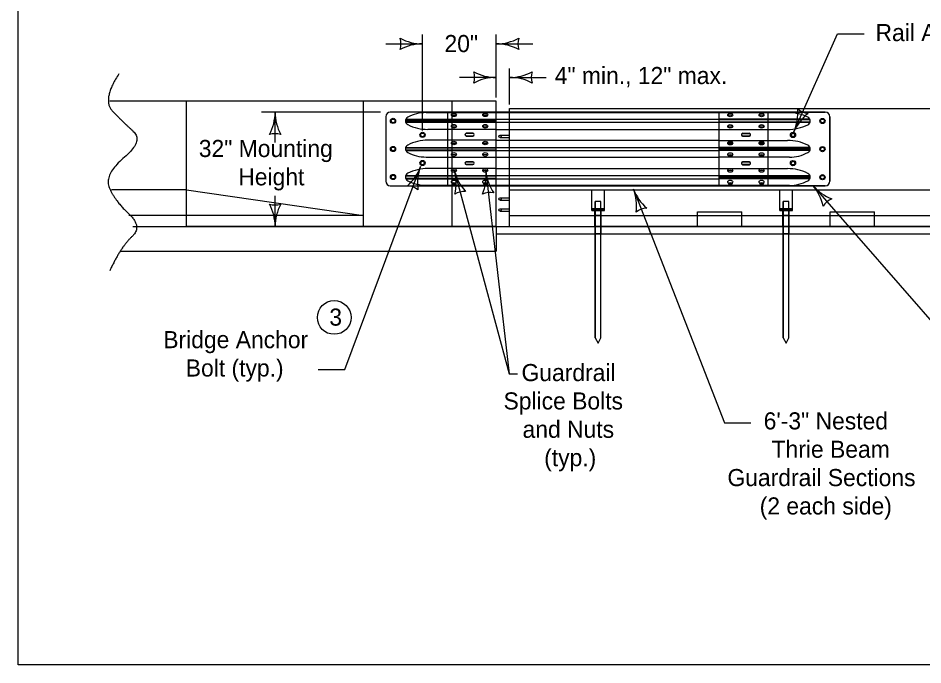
# Model space of a CAD drawing. Extents: x 10028 to 81668, y 3581 to 11018.
# Drawn here: x 20933 to 21737, y 7924 to 8499 of the extents above; entities that cross this region are included whole.
import ezdxf

# ---------------------------------------------------------------- set-up
doc = ezdxf.new("R2010")
doc.units = 0
for name, color, linetype in [('conPaving', 7, 'Continuous'), ('dsnCellsNorthArrow', 7, 'Continuous'), ('dsnTextTabulation', 7, 'Continuous'), ('Level 41', 7, 'Continuous'), ('Level 9', 7, 'Continuous'), ('SheetBorder', 7, 'Continuous')]:
    doc.layers.add(name, color=color, linetype=linetype)

msp = doc.modelspace()

# ---------------------------------------------------------------- linework, layer by layer
at = {"layer": 'conPaving'}
for p, q in [((21357.6, 8415.38), (21263.39, 8415.38)), ((21555.84, 8415.38), (21357.6, 8415.38)), ((21650.05, 8415.38), (21555.84, 8415.38)), ((21259.29, 8411.28), (21259.29, 8353.94)), ((21654.15, 8353.94), (21654.15, 8411.28)), ((21330.97, 8396.54), (21336.71, 8396.54)), ((21336.71, 8394.08), (21330.97, 8394.08)), ((21576.73, 8396.54), (21582.47, 8396.54)), ((21582.47, 8394.08), (21576.73, 8394.08)), ((21330.97, 8371.14), (21336.71, 8371.14)), ((21336.71, 8368.68), (21330.97, 8368.68)), ((21576.73, 8371.14), (21582.47, 8371.14)), ((21582.47, 8368.68), (21576.73, 8368.68)), ((21263.39, 8349.84), (21357.6, 8349.84)), ((21357.6, 8349.84), (21555.84, 8349.84)), ((21555.84, 8349.84), (21650.05, 8349.84)), ((21450.94, 8313.61), (21450.57, 8313.61)), ((21450.57, 8313.61), (21450.57, 8307.05)), ((21492.58, 8313.61), (21450.94, 8313.61)), ((21492.58, 8313.61), (21495.13, 8307.05)), ((21495.13, 8307.05), (21492.58, 8313.61)), ((21612.77, 8307.05), (21612.77, 8313.61)), ((21618.06, 8313.61), (21617.69, 8313.61)), ((21617.69, 8313.61), (21617.69, 8307.05)), ((21779.51, 8313.61), (21693.87, 8313.61)), ((21450.57, 8307.05), (21495.13, 8307.05)), ((21495.13, 8307.05), (21612.77, 8307.05)), ((21617.69, 8307.05), (21779.89, 8307.05))]:
    msp.add_line(p, q, dxfattribs=at)
for points in [[(21612.77, 8313.61), (21612.4, 8313.61), (21575.91, 8313.61), (21536.58, 8313.61), (21492.58, 8313.61)], [(21693.87, 8313.61), (21654.55, 8313.61), (21618.06, 8313.61)]]:
    msp.add_lwpolyline(points, dxfattribs=at)
for centre, radius, start, end in [((21263.39, 8411.28), 4.1, 90, 180), ((21650.05, 8411.28), 4.1, 0, 90), ((21330.97, 8395.31), 1.23, 90, 270), ((21336.71, 8395.31), 1.23, 270, 90), ((21576.73, 8395.31), 1.23, 90, 270), ((21582.47, 8395.31), 1.23, 270, 90), ((21330.97, 8369.91), 1.23, 90, 270), ((21336.71, 8369.91), 1.23, 270, 90), ((21576.73, 8369.91), 1.23, 90, 270), ((21582.47, 8369.91), 1.23, 270, 90), ((21263.39, 8353.94), 4.1, 180, 270), ((21650.05, 8353.94), 4.1, 270, 0)]:
    msp.add_arc(centre, radius, start, end, dxfattribs=at)
at = {"layer": 'dsnCellsNorthArrow'}
for p, q in [((21082.34, 8313.61), (21082.34, 8425.02)), ((21357.59, 8425.02), (21082.34, 8425.02)), ((21239.62, 8313.61), (21239.62, 8425.02)), ((21318.27, 8313.61), (21318.27, 8425.02)), ((21357.59, 8313.61), (21357.59, 8425.02)), ((21082.34, 8346.37), (21239.62, 8323.44)), ((21239.62, 8323.44), (21082.34, 8323.44)), ((21357.59, 8313.61), (21082.34, 8313.61))]:
    msp.add_line(p, q, dxfattribs=at)
at = {"layer": 'dsnTextTabulation'}
for p, q in [((21292.06, 8399.09), (21292.06, 8484.2)), ((21357.59, 8428.24), (21357.59, 8484.2)), ((21622.21, 8397.87), (21660.99, 8484.78)), ((21660.99, 8484.78), (21684.59, 8484.78)), ((21259.49, 8476), (21292.06, 8476)), ((21357.59, 8476), (21390.16, 8476)), ((21369.47, 8422.14), (21369.47, 8454.2)), ((21357.59, 8446.16), (21325.02, 8446.16)), ((21369.47, 8446.16), (21402.03, 8446.16)), ((21254.81, 8415.38), (21148.87, 8415.38)), ((21161.02, 8388.43), (21161.02, 8415.38)), ((21369.47, 8313.85), (21369.47, 8418.46)), ((21369.47, 8418.46), (21860.99, 8418.46)), ((21222.96, 8186.49), (21290.3, 8366.86)), ((21320.54, 8362.89), (21369.07, 8182.83)), ((21348.38, 8362.89), (21369.07, 8182.83)), ((21639.03, 8350.15), (21803.23, 8161.81)), ((21161.02, 8313.61), (21161.02, 8341.06)), ((21369.47, 8346.37), (21860.99, 8346.37)), ((21479.61, 8346.97), (21560.36, 8139.23)), ((21536.58, 8326.71), (21575.91, 8326.71)), ((21654.55, 8326.71), (21693.87, 8326.71)), ((21369.47, 8323.44), (21860.99, 8323.44)), ((21536.58, 8313.61), (21536.58, 8323.44)), ((21575.91, 8313.61), (21575.91, 8323.44)), ((21654.55, 8313.61), (21654.55, 8323.44)), ((21693.87, 8313.61), (21693.87, 8323.44)), ((21369.71, 8313.61), (21536.58, 8313.61)), ((21575.91, 8313.61), (21654.55, 8313.61)), ((21693.87, 8313.61), (21860.74, 8313.61)), ((21199.36, 8186.49), (21222.96, 8186.49)), ((21369.07, 8182.83), (21376.36, 8182.83)), ((21560.36, 8139.23), (21583.97, 8139.23))]:
    msp.add_line(p, q, dxfattribs=at)
msp.add_circle((21213.55, 8232.83), 15, dxfattribs=at)
for centre, radius, start, end in [((21256.42, 8476), 16.42, 342.26665, 17.73335), ((21292.06, 8518.5), 42.5, 241.92751, 270), ((21357.59, 8518.5), 42.5, 270, 298.07249), ((21393.22, 8476), 16.42, 162.26665, 197.73335), ((21292.06, 8433.5), 42.5, 90, 118.07249), ((21357.59, 8433.5), 42.5, 61.92751, 90), ((21321.95, 8446.16), 16.42, 342.26665, 17.73335), ((21357.59, 8488.66), 42.5, 241.92751, 270), ((21321.95, 8446.16), 16.42, 342.26665, 17.73335), ((21357.59, 8488.66), 42.5, 241.92751, 270), ((21357.59, 8403.66), 42.5, 90, 118.07249), ((21357.59, 8403.66), 42.5, 90, 118.07249), ((21369.47, 8488.66), 42.5, 270, 298.07249), ((21369.47, 8488.66), 42.5, 270, 298.07249), ((21369.47, 8403.66), 42.5, 61.92751, 90), ((21369.47, 8403.66), 42.5, 61.92751, 90), ((21405.1, 8446.16), 16.42, 162.26665, 197.73335), ((21405.1, 8446.16), 16.42, 162.26665, 197.73335), ((21118.52, 8415.38), 42.5, 331.92751, 360), ((21203.52, 8415.38), 42.5, 180, 208.07249), ((21583.2, 8414.75), 42.5, 336.60184, 4.67433), ((21661.21, 8381), 42.5, 128.52935, 156.60184), ((21636.36, 8430.58), 16.42, 228.86849, 264.33519), ((21161.02, 8379.74), 16.42, 72.26665, 107.73335), ((21250.49, 8381.73), 42.5, 311.45357, 339.52606), ((21330.12, 8352), 42.5, 159.52606, 187.59855), ((21279.38, 8352.29), 42.5, 346.36285, 14.43534), ((21361.7, 8373.48), 42.5, 194.43534, 222.50783), ((21306.1, 8358.52), 42.5, 337.83385, 5.90634), ((21390.65, 8367.27), 42.5, 185.90634, 213.97883), ((21277.84, 8333.48), 16.42, 51.79271, 87.25941), ((21606.68, 8322.59), 42.5, 12.36113, 40.43362), ((21671.38, 8377.71), 42.5, 220.43362, 248.50611), ((21329.42, 8328.37), 16.42, 86.70199, 122.16869), ((21352.05, 8327.45), 16.42, 78.17299, 113.63969), ((21439.83, 8332.02), 42.5, 352.52075, 20.59324), ((21519.39, 8361.92), 42.5, 200.59324, 228.66573), ((21161.02, 8349.24), 16.42, 252.26665, 287.73335), ((21118.52, 8313.61), 42.5, 360, 28.07249), ((21203.52, 8313.61), 42.5, 151.92751, 180), ((21662.14, 8323.03), 16.42, 112.70027, 148.16697), ((21492.14, 8313.61), 16.42, 92.85989, 128.32659)]:
    msp.add_arc(centre, radius, start, end, dxfattribs=at)
at = {"layer": 'Level 41'}
for p, q in [((21360.97, 8394.95), (21369.47, 8394.95)), ((21360.97, 8392.83), (21369.47, 8392.83)), ((21442.45, 8327.81), (21442.45, 8346.37)), ((21453.77, 8327.81), (21453.77, 8346.37)), ((21609.57, 8327.81), (21609.57, 8346.37)), ((21620.89, 8327.81), (21620.89, 8346.37)), ((21360.97, 8339.24), (21369.46, 8339.24)), ((21360.97, 8337.12), (21369.46, 8337.12)), ((21360.97, 8329.41), (21369.46, 8329.41)), ((21360.97, 8327.29), (21369.46, 8327.29)), ((21442.45, 8327.81), (21453.77, 8327.81)), ((21445.28, 8313.61), (21445.28, 8327.81)), ((21450.94, 8313.61), (21450.94, 8327.81)), ((21609.57, 8327.81), (21620.89, 8327.81)), ((21612.4, 8313.61), (21612.4, 8327.81)), ((21618.06, 8313.61), (21618.06, 8327.81))]:
    msp.add_line(p, q, dxfattribs=at)
for centre in [(21360.97, 8393.89), (21360.97, 8338.18), (21360.97, 8328.35)]:
    msp.add_circle(centre, 1.06, dxfattribs=at)
at = {"layer": 'Level 9'}
for p, q in [((21082.34, 8425.02), (21014.19, 8425.02)), ((21357.6, 8415.38), (21263.39, 8415.38)), ((21357.6, 8415.38), (21263.39, 8415.38)), ((21314.18, 8415.38), (21314.18, 8349.84)), ((21357.6, 8349.84), (21357.6, 8415.38)), ((21555.84, 8415.38), (21650.05, 8415.38)), ((21555.84, 8349.84), (21555.84, 8415.38)), ((21599.26, 8349.73), (21599.26, 8415.27)), ((21259.29, 8411.28), (21259.29, 8353.94)), ((21259.29, 8411.28), (21259.29, 8353.94)), ((21357.6, 8406.93), (21276.83, 8406.93)), ((21276.9, 8408.46), (21357.6, 8408.46)), ((21277, 8406.32), (21357.6, 8406.32)), ((21277.13, 8409.08), (21357.6, 8409.08)), ((21636.31, 8408.96), (21555.84, 8408.96)), ((21636.53, 8408.35), (21555.84, 8408.35)), ((21555.84, 8406.82), (21636.6, 8406.82)), ((21636.44, 8406.21), (21555.84, 8406.21)), ((21654.15, 8411.28), (21654.15, 8353.94)), ((21654.15, 8411.28), (21654.15, 8353.94)), ((21357.6, 8383.38), (21276.83, 8383.38)), ((21276.9, 8381.84), (21357.6, 8381.84)), ((21277, 8383.99), (21357.6, 8383.99)), ((21277.13, 8381.23), (21357.6, 8381.23)), ((21636.44, 8383.88), (21555.84, 8383.88)), ((21555.84, 8383.27), (21636.6, 8383.27)), ((21636.53, 8381.73), (21555.84, 8381.73)), ((21636.31, 8381.12), (21555.84, 8381.12)), ((21357.6, 8358.29), (21276.83, 8358.29)), ((21277, 8358.91), (21357.6, 8358.91)), ((21636.44, 8358.79), (21555.84, 8358.79)), ((21555.84, 8358.18), (21636.6, 8358.18)), ((21263.39, 8349.84), (21357.6, 8349.84)), ((21263.39, 8349.84), (21357.6, 8349.84)), ((21276.9, 8356.76), (21357.6, 8356.76)), ((21277.13, 8356.15), (21357.6, 8356.15)), ((21357.6, 8349.84), (21555.84, 8349.84)), ((21357.6, 8349.84), (21555.84, 8349.84)), ((21636.53, 8356.65), (21555.84, 8356.65)), ((21636.31, 8356.04), (21555.84, 8356.04)), ((21650.05, 8349.84), (21555.84, 8349.84)), ((21082.34, 8346.37), (21015.45, 8346.37)), ((21450.57, 8336), (21445.65, 8336)), ((21445.65, 8336), (21445.65, 8329.45)), ((21450.57, 8336), (21445.65, 8336)), ((21445.65, 8214.76), (21445.65, 8336)), ((21450.57, 8329.45), (21450.57, 8336)), ((21450.57, 8214.76), (21450.57, 8336)), ((21617.69, 8336), (21612.77, 8336)), ((21612.77, 8336), (21612.77, 8329.45)), ((21617.69, 8336), (21612.77, 8336)), ((21612.77, 8214.76), (21612.77, 8336)), ((21617.69, 8329.45), (21617.69, 8336)), ((21617.69, 8214.76), (21617.69, 8336)), ((21443.2, 8329.45), (21443.2, 8327.81)), ((21445.65, 8329.45), (21443.2, 8329.45)), ((21443.2, 8327.81), (21443.2, 8329.45)), ((21443.2, 8327.81), (21445.28, 8327.81)), ((21445.28, 8327.81), (21445.65, 8327.81)), ((21450.57, 8329.45), (21445.65, 8329.45)), ((21445.65, 8329.45), (21445.65, 8327.81)), ((21445.65, 8327.81), (21445.65, 8329.45)), ((21445.65, 8329.45), (21450.57, 8329.45)), ((21450.57, 8327.81), (21445.65, 8327.81)), ((21445.65, 8327.81), (21445.65, 8323.44)), ((21445.65, 8327.81), (21450.57, 8327.81)), ((21450.57, 8327.81), (21450.57, 8329.45)), ((21450.57, 8329.45), (21450.57, 8327.81)), ((21450.57, 8323.44), (21450.57, 8327.81)), ((21536.58, 8323.44), (21536.58, 8326.71)), ((21575.91, 8323.44), (21575.91, 8326.71)), ((21610.31, 8329.45), (21610.31, 8327.81)), ((21612.77, 8329.45), (21610.31, 8329.45)), ((21610.31, 8327.81), (21610.31, 8329.45)), ((21610.31, 8327.81), (21612.4, 8327.81)), ((21612.4, 8327.81), (21612.77, 8327.81)), ((21617.69, 8329.45), (21612.77, 8329.45)), ((21612.77, 8329.45), (21612.77, 8327.81)), ((21612.77, 8327.81), (21612.77, 8329.45)), ((21612.77, 8329.45), (21617.69, 8329.45)), ((21617.69, 8327.81), (21612.77, 8327.81)), ((21612.77, 8327.81), (21612.77, 8323.44)), ((21612.77, 8327.81), (21617.69, 8327.81)), ((21617.69, 8327.81), (21617.69, 8329.45)), ((21617.69, 8329.45), (21617.69, 8327.81)), ((21617.69, 8323.44), (21617.69, 8327.81)), ((21654.55, 8323.44), (21654.55, 8326.71)), ((21693.87, 8323.44), (21693.87, 8326.71)), ((21082.34, 8323.44), (21031.11, 8323.44)), ((21450.57, 8323.44), (21445.65, 8323.44)), ((21445.65, 8323.44), (21445.65, 8313.61)), ((21445.65, 8323.44), (21450.57, 8323.44)), ((21450.57, 8313.61), (21450.57, 8323.44)), ((21536.58, 8323.44), (21575.91, 8323.44)), ((21617.69, 8323.44), (21612.77, 8323.44)), ((21612.77, 8323.44), (21612.77, 8313.61)), ((21612.77, 8323.44), (21617.69, 8323.44)), ((21617.69, 8313.61), (21617.69, 8323.44)), ((21654.55, 8323.44), (21693.87, 8323.44)), ((21034.39, 8313.61), (23909.19, 8313.61)), ((21357.59, 8313.61), (21357.59, 8307.05)), ((21357.59, 8313.61), (21357.59, 8291.66)), ((21369.47, 8313.85), (21369.71, 8313.61)), ((21450.57, 8313.61), (21445.65, 8313.61)), ((21445.65, 8313.61), (21445.65, 8307.05)), ((21445.65, 8313.61), (21450.57, 8313.61)), ((21450.57, 8307.05), (21450.57, 8313.61)), ((21617.69, 8313.61), (21612.77, 8313.61)), ((21612.77, 8313.61), (21612.77, 8307.05)), ((21612.77, 8313.61), (21617.69, 8313.61)), ((21617.69, 8307.05), (21617.69, 8313.61)), ((21357.59, 8307.05), (23377.13, 8307.05)), ((21450.57, 8307.05), (21445.65, 8307.05)), ((21445.65, 8307.05), (21445.65, 8214.76)), ((21445.65, 8307.05), (21450.57, 8307.05)), ((21450.57, 8214.76), (21450.57, 8307.05)), ((21617.69, 8307.05), (21612.77, 8307.05)), ((21612.77, 8307.05), (21612.77, 8214.76)), ((21612.77, 8307.05), (21617.69, 8307.05)), ((21617.69, 8214.76), (21617.69, 8307.05)), ((21023.32, 8291.66), (21357.59, 8291.66)), ((21445.65, 8214.76), (21448.11, 8209.84)), ((21445.65, 8214.76), (21448.11, 8209.84)), ((21448.11, 8209.84), (21450.57, 8214.76)), ((21448.11, 8209.84), (21450.57, 8214.76)), ((21612.77, 8214.76), (21615.23, 8209.84)), ((21612.77, 8214.76), (21615.23, 8209.84)), ((21615.23, 8209.84), (21617.69, 8214.76)), ((21615.23, 8209.84), (21617.69, 8214.76))]:
    msp.add_line(p, q, dxfattribs=at)
for points in [[(21295.19, 8414.88), (21357.6, 8414.88)], [(21357.6, 8415.38), (21555.84, 8415.38)], [(21357.6, 8414.88), (21555.84, 8414.88)], [(21618.25, 8414.77), (21555.84, 8414.77)], [(21357.6, 8409.08), (21555.84, 8409.08)], [(21357.6, 8406.32), (21555.84, 8406.32)], [(21357.6, 8399.97), (21296.82, 8399.97)], [(21357.6, 8399.97), (21555.84, 8399.97)], [(21555.84, 8399.86), (21616.62, 8399.86)], [(21357.6, 8390.34), (21296.82, 8390.34)], [(21336.71, 8396.54), (21330.97, 8396.54)], [(21336.71, 8396.54), (21330.97, 8396.54)], [(21330.97, 8394.08), (21336.71, 8394.08)], [(21330.97, 8394.08), (21336.71, 8394.08)], [(21357.6, 8390.34), (21555.84, 8390.34)], [(21555.84, 8390.23), (21616.62, 8390.23)], [(21576.73, 8396.43), (21582.47, 8396.43)], [(21582.47, 8396.43), (21576.73, 8396.43)], [(21576.73, 8396.43), (21582.47, 8396.43)], [(21582.47, 8396.43), (21576.73, 8396.43)], [(21582.47, 8393.97), (21576.73, 8393.97)], [(21576.73, 8393.97), (21582.47, 8393.97)], [(21582.47, 8393.97), (21576.73, 8393.97)], [(21576.73, 8393.97), (21582.47, 8393.97)], [(21357.6, 8383.99), (21555.84, 8383.99)], [(21357.6, 8381.23), (21555.84, 8381.23)], [(21295.19, 8375.42), (21357.6, 8375.42)], [(21357.6, 8375.42), (21555.84, 8375.42)], [(21618.25, 8375.31), (21555.84, 8375.31)], [(21357.6, 8365.26), (21296.82, 8365.26)], [(21336.71, 8371.14), (21330.97, 8371.14)], [(21336.71, 8371.14), (21330.97, 8371.14)], [(21330.97, 8368.68), (21336.71, 8368.68)], [(21330.97, 8368.68), (21336.71, 8368.68)], [(21357.6, 8365.26), (21555.84, 8365.26)], [(21555.84, 8365.14), (21616.62, 8365.14)], [(21576.73, 8371.03), (21582.47, 8371.03)], [(21582.47, 8371.03), (21576.73, 8371.03)], [(21576.73, 8371.03), (21582.47, 8371.03)], [(21582.47, 8371.03), (21576.73, 8371.03)], [(21582.47, 8368.57), (21576.73, 8368.57)], [(21576.73, 8368.57), (21582.47, 8368.57)], [(21582.47, 8368.57), (21576.73, 8368.57)], [(21576.73, 8368.57), (21582.47, 8368.57)], [(21357.6, 8358.91), (21555.84, 8358.91)], [(21295.19, 8350.34), (21357.6, 8350.34)], [(21357.6, 8356.15), (21555.84, 8356.15)], [(21357.6, 8350.34), (21555.84, 8350.34)], [(21618.25, 8350.23), (21555.84, 8350.23)], [(21443.2, 8329.45), (21453.03, 8329.45), (21453.03, 8327.81), (21443.2, 8327.81)], [(21453.03, 8327.81), (21453.03, 8329.45), (21450.57, 8329.45)], [(21450.57, 8327.81), (21450.94, 8327.81), (21453.03, 8327.81)], [(21610.31, 8329.45), (21620.14, 8329.45), (21620.14, 8327.81), (21610.31, 8327.81)], [(21620.14, 8327.81), (21620.14, 8329.45), (21617.69, 8329.45)], [(21617.69, 8327.81), (21618.06, 8327.81), (21620.14, 8327.81)]]:
    msp.add_lwpolyline(points, dxfattribs=at)
for centre, radius in [((21265.84, 8407.58), 2.3), ((21265.84, 8407.58), 1.64), ((21265.84, 8407.58), 1.64), ((21647.59, 8407.47), 2.3), ((21647.59, 8407.47), 1.64), ((21647.59, 8407.47), 1.64), ((21292.06, 8395.1), 2.3), ((21292.06, 8395.1), 1.64), ((21292.06, 8395.1), 1.64), ((21621.38, 8394.99), 2.3), ((21621.38, 8394.99), 1.64), ((21621.38, 8394.99), 1.64), ((21265.84, 8382.59), 2.3), ((21265.84, 8382.59), 1.64), ((21265.84, 8382.59), 1.64), ((21647.59, 8382.48), 2.3), ((21647.59, 8382.48), 1.64), ((21647.59, 8382.48), 1.64), ((21292.06, 8370.12), 2.3), ((21292.06, 8370.12), 1.64), ((21292.06, 8370.12), 1.64), ((21621.38, 8370.01), 2.3), ((21621.38, 8370.01), 1.64), ((21621.38, 8370.01), 1.64), ((21265.84, 8357.63), 2.3), ((21265.84, 8357.63), 1.64), ((21265.84, 8357.63), 1.64), ((21647.59, 8357.51), 2.3), ((21647.59, 8357.51), 1.64), ((21647.59, 8357.51), 1.64)]:
    msp.add_circle(centre, radius, dxfattribs=at)
for centre, radius, start, end in [((21263.39, 8411.28), 4.1, 90, 180), ((21263.39, 8411.28), 4.1, 90, 180), ((21294.72, 8382.18), 32.71, 89.18232, 118.89051), ((21618.72, 8382.07), 32.71, 61.10949, 90.81768), ((21650.05, 8411.28), 4.1, 0, 90), ((21650.05, 8411.28), 4.1, 0, 90), ((21280.37, 8407.53), 3.59, 113.8801, 246.1199), ((21633.07, 8407.42), 3.59, 293.8801, 66.1199), ((21296.78, 8439.34), 39.37, 243.01498, 270.05598), ((21616.65, 8439.23), 39.37, 269.94402, 296.98502), ((21296.78, 8350.97), 39.37, 89.94402, 116.98502), ((21330.97, 8395.31), 1.23, 90, 270), ((21330.97, 8395.31), 1.23, 90, 270), ((21336.71, 8395.31), 1.23, 270, 90), ((21336.71, 8395.31), 1.23, 270, 90), ((21576.73, 8395.2), 1.23, 90, 270), ((21576.73, 8395.2), 1.23, 90, 270), ((21576.73, 8395.2), 1.23, 90, 270), ((21576.73, 8395.2), 1.23, 90, 270), ((21582.47, 8395.2), 1.23, 270, 90), ((21582.47, 8395.2), 1.23, 270, 90), ((21582.47, 8395.2), 1.23, 270, 90), ((21582.47, 8395.2), 1.23, 270, 90), ((21616.65, 8350.86), 39.37, 63.01498, 90.05598), ((21280.37, 8382.77), 3.59, 113.8801, 246.1199), ((21633.07, 8382.66), 3.59, 293.8801, 66.1199), ((21294.72, 8408.13), 32.71, 241.10949, 270.81768), ((21618.72, 8408.02), 32.71, 269.18232, 298.89051), ((21296.78, 8325.88), 39.37, 89.94402, 116.98502), ((21330.97, 8369.91), 1.23, 90, 270), ((21330.97, 8369.91), 1.23, 90, 270), ((21336.71, 8369.91), 1.23, 270, 90), ((21336.71, 8369.91), 1.23, 270, 90), ((21576.73, 8369.8), 1.23, 90, 270), ((21576.73, 8369.8), 1.23, 90, 270), ((21576.73, 8369.8), 1.23, 90, 270), ((21576.73, 8369.8), 1.23, 90, 270), ((21582.47, 8369.8), 1.23, 270, 90), ((21582.47, 8369.8), 1.23, 270, 90), ((21582.47, 8369.8), 1.23, 270, 90), ((21582.47, 8369.8), 1.23, 270, 90), ((21616.65, 8325.77), 39.37, 63.01498, 90.05598), ((21280.37, 8357.69), 3.59, 113.8801, 246.1199), ((21633.07, 8357.58), 3.59, 293.8801, 66.1199), ((21263.39, 8353.94), 4.1, 180, 270), ((21263.39, 8353.94), 4.1, 180, 270), ((21294.72, 8383.04), 32.71, 241.10949, 270.81768), ((21618.72, 8382.93), 32.71, 269.18232, 298.89051), ((21650.05, 8353.94), 4.1, 270, 0), ((21650.05, 8353.94), 4.1, 270, 0)]:
    msp.add_arc(centre, radius, start, end, dxfattribs=at)
for centre, major_axis, ratio in [((21319.94, 8412.85), (-2.26, 0), 0.685714), ((21319.93, 8413.29), (-1.84, 0), 0.456281), ((21347.8, 8412.85), (-2.26, 0), 0.685714), ((21347.77, 8413.28), (-1.84, 0), 0.456281), ((21565.63, 8412.74), (2.26, 0), 0.685714), ((21565.67, 8413.17), (1.84, 0), 0.456281), ((21593.5, 8412.74), (2.26, 0), 0.685714), ((21593.51, 8413.18), (1.84, 0), 0.456281), ((21319.94, 8402.76), (-2.26, 0), 0.685714), ((21319.91, 8402.34), (-1.84, 0), 0.456281), ((21347.8, 8402.76), (-2.26, 0), 0.685714), ((21347.75, 8402.33), (-1.84, 0), 0.456281), ((21565.63, 8402.65), (2.26, 0), 0.685714), ((21565.69, 8402.22), (1.84, 0), 0.456281), ((21593.5, 8402.65), (2.26, 0), 0.685714), ((21593.53, 8402.23), (1.84, 0), 0.456281), ((21319.94, 8387.86), (-2.26, 0), 0.685714), ((21347.8, 8387.86), (-2.26, 0), 0.685714), ((21565.63, 8387.75), (2.26, 0), 0.685714), ((21593.5, 8387.75), (2.26, 0), 0.685714), ((21319.91, 8387.97), (-1.84, 0), 0.456281), ((21347.75, 8387.98), (-1.84, 0), 0.456281), ((21565.69, 8387.87), (1.84, 0), 0.456281), ((21593.53, 8387.86), (1.84, 0), 0.456281), ((21319.94, 8377.76), (-2.26, 0), 0.685714), ((21319.93, 8377.02), (-1.84, 0), 0.456281), ((21347.8, 8377.76), (-2.26, 0), 0.685714), ((21347.77, 8377.03), (-1.84, 0), 0.456281), ((21565.63, 8377.65), (2.26, 0), 0.685714), ((21565.67, 8376.92), (1.84, 0), 0.456281), ((21593.5, 8377.65), (2.26, 0), 0.685714), ((21593.51, 8376.91), (1.84, 0), 0.456281), ((21319.94, 8363.52), (-2.26, 0), 0.685714), ((21319.91, 8362.89), (-1.84, 0), 0.456281), ((21347.8, 8363.52), (-2.26, 0), 0.685714), ((21347.75, 8362.89), (-1.84, 0), 0.456281), ((21565.63, 8363.41), (2.26, 0), 0.685714), ((21565.69, 8362.78), (1.84, 0), 0.456281), ((21593.5, 8363.41), (2.26, 0), 0.685714), ((21593.53, 8362.78), (1.84, 0), 0.456281), ((21319.94, 8353.42), (-2.26, 0), 0.685714), ((21319.93, 8351.93), (-1.84, 0), 0.456281), ((21347.8, 8353.42), (-2.26, 0), 0.685714), ((21347.77, 8351.94), (-1.84, 0), 0.456281), ((21565.63, 8353.31), (2.26, 0), 0.685714), ((21565.67, 8351.83), (1.84, 0), 0.456281), ((21593.5, 8353.31), (2.26, 0), 0.685714), ((21593.51, 8351.82), (1.84, 0), 0.456281)]:
    msp.add_ellipse(centre, major_axis=major_axis, ratio=ratio, dxfattribs=at)
msp.add_open_spline([(21022.07, 8449.28), (21006.99, 8426.2), (21025.62, 8406.67), (21044.26, 8389.8), (21008.76, 8359.61), (21018.52, 8336.52), (21043.37, 8313.44), (21023.85, 8295.68), (21014.09, 8274.37)], degree=2, dxfattribs=at)
at = {"layer": 'SheetBorder'}
msp.add_lwpolyline([(20932.52, 9944.02), (24067.53, 9944.02), (24067.53, 7924.02), (20932.52, 7924.02)], close=True, dxfattribs=at)

# ---------------------------------------------------------------- texts
at = {"layer": 'dsnCellsNorthArrow'}
for s, p in [('Rail Anchor Bolt', (21694.72, 8478.43)), ('20"', (21311.57, 8468.69)), ('4" min., 12" max.', (21409.57, 8440.26)), ('32" Mounting', (21093.17, 8375.43)), ('Height', (21128.27, 8350.23)), ('Bridge Anchor', (21061.6, 8205.53)), ('Bolt (typ.)', (21081.58, 8180.33)), ('Guardrail', (21380.03, 8176.24)), ('Splice Bolts', (21364.06, 8151.04)), ('6\'-3" Nested', (21595.32, 8133.31)), ('and Nuts', (21380.97, 8125.84)), ('Thrie Beam', (21602.35, 8108.11)), ('(typ.)', (21400.2, 8100.64)), ('Guardrail Sections', (21563.09, 8082.91)), ('(2 each side)', (21591.77, 8057.71))]:
    msp.add_text(s, height=15.2, dxfattribs=at).set_placement(p)
at = {"layer": 'dsnTextTabulation'}
msp.add_text('3', height=15.2, dxfattribs=at).set_placement((21209.18, 8225.54))

doc.saveas('drawing.dxf')
